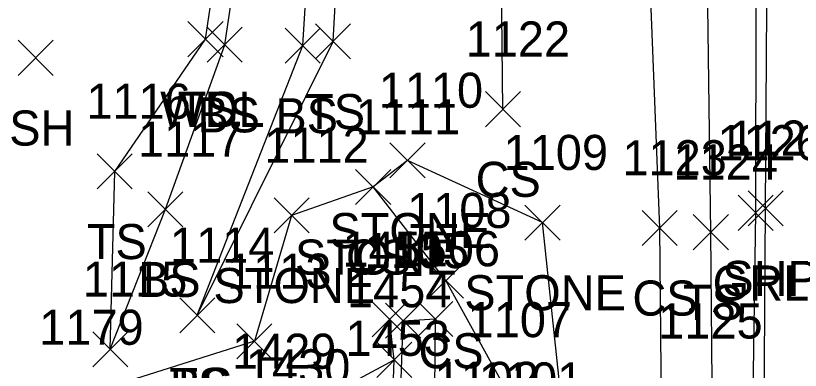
# Model space of a CAD drawing. Extents: x 1618262 to 1622220, y 273782 to 283685.
# Drawn here: x 1622001.44 to 1622046.16, y 282700.39 to 282720.6 of the extents above; entities that cross this region are included whole.
import ezdxf

# ---------------------------------------------------------------- set-up
doc = ezdxf.new("R2010")
doc.units = 0
for name, color, linetype in [('D_I', 7, 'Continuous'), ('D_TIC', 7, 'Continuous'), ('DHW', 7, 'Continuous'), ('L_A', 7, 'Continuous'), ('L_I', 7, 'Continuous'), ('L_TIC', 7, 'Continuous'), ('LASF', 7, 'Continuous'), ('LAWA', 7, 'Continuous'), ('LAWE', 7, 'Continuous'), ('LELB', 7, 'Continuous'), ('P_A', 7, 'Continuous'), ('P_I', 7, 'Continuous'), ('P_TIC', 7, 'Continuous'), ('PSP', 7, 'Continuous'), ('R_A', 7, 'Continuous'), ('R_I', 7, 'Continuous'), ('R_TIC', 7, 'Continuous'), ('RGR', 7, 'Continuous'), ('S_I', 7, 'Continuous')]:
    doc.layers.add(name, color=color, linetype=linetype)

msp = doc.modelspace()

# ---------------------------------------------------------------- linework, layer by layer
at = {"layer": 'D_TIC'}
for points in [[(1622022.527, 282702.211), (1622024.527, 282704.211)], [(1622024.527, 282702.211), (1622022.527, 282704.211)], [(1622024.354, 282702.314), (1622026.354, 282704.314)], [(1622026.354, 282702.314), (1622024.354, 282704.314)]]:
    msp.add_lwpolyline(points, dxfattribs=at)
at = {"layer": 'DHW'}
msp.add_lwpolyline([(1622025.278, 282695.241), (1622023.237, 282694.874), (1622023.527, 282703.211), (1622025.354, 282703.314), (1622025.278, 282695.241)], dxfattribs=at)
at = {"layer": 'L_TIC'}
for points in [[(1622011.261, 282718.262), (1622013.261, 282720.262)], [(1622013.261, 282718.262), (1622011.261, 282720.262)], [(1622011.261, 282718.262), (1622013.261, 282720.262)], [(1622013.261, 282718.262), (1622011.261, 282720.262)], [(1622018.526, 282718.135), (1622020.526, 282720.135)], [(1622020.526, 282718.135), (1622018.526, 282720.135)], [(1622012.354, 282717.948), (1622014.354, 282719.948)], [(1622014.354, 282717.948), (1622012.354, 282719.948)], [(1622016.803, 282717.897), (1622018.803, 282719.897)], [(1622018.803, 282717.897), (1622016.803, 282719.897)], [(1622001.585, 282717.197), (1622003.585, 282719.197)], [(1622003.585, 282717.197), (1622001.585, 282719.197)], [(1622028.212, 282714.273), (1622030.212, 282716.273)], [(1622030.212, 282714.273), (1622028.212, 282716.273)], [(1622022.774, 282711.352), (1622024.774, 282713.352)], [(1622024.774, 282711.352), (1622022.774, 282713.352)], [(1622006.086, 282710.724), (1622008.086, 282712.724)], [(1622008.086, 282710.724), (1622006.086, 282712.724)], [(1622020.815, 282709.839), (1622022.815, 282711.839)], [(1622022.815, 282709.839), (1622020.815, 282711.839)], [(1622020.815, 282709.839), (1622022.815, 282711.839)], [(1622022.815, 282709.839), (1622020.815, 282711.839)], [(1622008.972, 282708.565), (1622010.972, 282710.565)], [(1622010.972, 282708.565), (1622008.972, 282710.565)], [(1622016.17, 282708.218), (1622018.17, 282710.218)], [(1622018.17, 282708.218), (1622016.17, 282710.218)], [(1622030.462, 282707.807), (1622032.462, 282709.807)], [(1622032.462, 282707.807), (1622030.462, 282709.807)], [(1622037.146, 282707.503), (1622039.146, 282709.503)], [(1622039.146, 282707.503), (1622037.146, 282709.503)], [(1622040.057, 282707.261), (1622042.057, 282709.261)], [(1622042.057, 282707.261), (1622040.057, 282709.261)], [(1622024.954, 282704.5), (1622026.954, 282706.5)], [(1622026.954, 282704.5), (1622024.954, 282706.5)], [(1622010.792, 282702.523), (1622012.792, 282704.523)], [(1622012.792, 282702.523), (1622010.792, 282704.523)], [(1622010.792, 282702.523), (1622012.792, 282704.523)], [(1622012.792, 282702.523), (1622010.792, 282704.523)], [(1622021.752, 282702.296), (1622023.752, 282704.296)], [(1622023.752, 282702.296), (1622021.752, 282704.296)], [(1622014.049, 282701.038), (1622016.049, 282703.038)], [(1622016.049, 282701.038), (1622014.049, 282703.038)], [(1622005.83, 282700.587), (1622007.83, 282702.587)], [(1622007.83, 282700.587), (1622005.83, 282702.587)], [(1622005.83, 282700.587), (1622007.83, 282702.587)], [(1622007.83, 282700.587), (1622005.83, 282702.587)], [(1622022.015, 282699.983), (1622024.015, 282701.983)], [(1622024.015, 282699.983), (1622022.015, 282701.983)], [(1622022.015, 282699.983), (1622024.015, 282701.983)], [(1622024.015, 282699.983), (1622022.015, 282701.983)]]:
    msp.add_lwpolyline(points, dxfattribs=at)
at = {"layer": 'LASF'}
msp.add_lwpolyline([(1622017.991, 282482.049), (1622021.545, 282521.435), (1622023.199, 282560.154), (1622027.724, 282598.268), (1622026.162, 282633.945), (1622026.882, 282675.285), (1622029.94, 282679.448), (1622032.966, 282688.79), (1622033.094, 282693.395), (1622031.462, 282708.807), (1622023.774, 282712.352), (1622021.815, 282710.839), (1622017.17, 282709.218), (1622015.049, 282702.038), (1622004.918, 282698.84), (1621996.66, 282681.559), (1622000.409, 282659.069)], dxfattribs=at)
at = {"layer": 'LAWA'}
msp.add_lwpolyline([(1622012.261, 282719.262), (1622015.512, 282741.117), (1622016.402, 282766.923), (1622013.003, 282796.989), (1622009.949, 282826.463), (1622001.868, 282858.825)], dxfattribs=at)
at = {"layer": 'LAWE'}
msp.add_lwpolyline([(1622004.508, 282589.719), (1622005.333, 282608.569), (1622007.513, 282631.716), (1622009.259, 282658.274), (1622005.37, 282679.941), (1622009.389, 282692.601), (1622016.472, 282697.474), (1622023.015, 282700.983)], dxfattribs=at)
at = {"layer": 'LELB'}
for points in [[(1622031.53, 282480.209), (1622034.92, 282519.516), (1622036.308, 282559.668), (1622038.549, 282600.481), (1622040.575, 282634.794), (1622041.384, 282671.626), (1622041.057, 282708.261), (1622040.536, 282746.865), (1622039.334, 282766.475), (1622038.366, 282807.145), (1622036.997, 282847.689), (1622035.465, 282881.364), (1622030.123, 282906.905), (1622032.201, 282930.97)], [(1622011.792, 282703.523), (1622017.803, 282718.897), (1622019.25, 282742.062), (1622019.347, 282767.736), (1622022.846, 282795.877), (1622021.207, 282825.793), (1622021.001, 282858.668), (1622021.577, 282889.835), (1622019.372, 282916.251), (1622019.074, 282930.132)], [(1622006.83, 282701.587), (1622009.972, 282709.565), (1622013.354, 282718.948), (1622016.651, 282741.117), (1622017.648, 282766.711), (1622013.003, 282796.989)], [(1622011.792, 282703.523), (1622019.526, 282719.135), (1622020.798, 282741.845), (1622019.651, 282767.692), (1622022.846, 282795.877)], [(1622038.036, 282634.62), (1622038.492, 282672.044), (1622038.146, 282708.503), (1622036.634, 282747.032), (1622027.782, 282767.08)], [(1622029.212, 282715.273), (1622028.888, 282746.116), (1622027.782, 282767.08)], [(1622006.83, 282701.587), (1622007.086, 282711.724), (1622012.261, 282719.262)], [(1622029.403, 282699.274), (1622025.954, 282705.5), (1622021.815, 282710.839)], [(1622015.253, 282589.258), (1622018.278, 282610.651), (1622017.432, 282626.905), (1622019.353, 282657.587), (1622018.302, 282675.18), (1622022.753, 282682.471), (1622023.259, 282685.553), (1622022.974, 282687.958), (1622023.158, 282690.363), (1622022.911, 282694.814), (1622022.926, 282698.21), (1622023.015, 282700.983), (1622022.752, 282703.296)]]:
    msp.add_lwpolyline(points, dxfattribs=at)
at = {"layer": 'P_TIC'}
for points in [[(1622043.179, 282708.624), (1622045.179, 282710.624)], [(1622045.179, 282708.624), (1622043.179, 282710.624)]]:
    msp.add_lwpolyline(points, dxfattribs=at)
at = {"layer": 'PSP'}
msp.add_lwpolyline([(1622024.53, 282364.695), (1622029.224, 282410.341), (1622032.133, 282444.404), (1622034.721, 282480.169), (1622038.065, 282518.937), (1622040.189, 282559.981), (1622041.775, 282599.797), (1622043.576, 282635.077), (1622043.931, 282671.705), (1622044.179, 282709.624), (1622044.427, 282746.882), (1622044.138, 282766.852), (1622043.312, 282807.356), (1622042.106, 282847.846), (1622040.006, 282882.115), (1622036.278, 282931.352)], dxfattribs=at)
at = {"layer": 'R_TIC'}
for points in [[(1622042.615, 282708.363), (1622044.615, 282710.363)], [(1622044.615, 282708.363), (1622042.615, 282710.363)]]:
    msp.add_lwpolyline(points, dxfattribs=at)
at = {"layer": 'RGR'}
msp.add_lwpolyline([(1622023.476, 282364.894), (1622028.185, 282410.184), (1622031.232, 282444.188), (1622033.737, 282480.242), (1622036.802, 282518.899), (1622039.036, 282560.065), (1622040.978, 282599.772), (1622042.921, 282635.171), (1622043.063, 282671.763), (1622043.615, 282709.363), (1622043.681, 282746.97), (1622043.35, 282766.727), (1622042.763, 282807.193), (1622041.251, 282847.718), (1622039.436, 282882.181), (1622035.129, 282907.981)], dxfattribs=at)

# ---------------------------------------------------------------- texts
at = {"layer": 'D_I'}
for s, p in [('1105', (1622021.323, 282706.211)), ('1106', (1622023.094, 282706.314))]:
    msp.add_text(s, height=2, dxfattribs=at).set_placement(p)
at = {"layer": 'L_A'}
for s, p in [('WDL', (1622009.679, 282714.262)), ('TS', (1622010.671, 282714.262)), ('TS', (1622017.935, 282714.135)), ('BS', (1622011.795, 282713.948)), ('BS', (1622016.244, 282713.897)), ('SH', (1622001.074, 282713.197)), ('CS', (1622027.653, 282710.273)), ('STONE', (1622019.318, 282707.352)), ('TS', (1622005.495, 282706.724)), ('STONE', (1622017.358, 282705.839)), ('CS', (1622020.256, 282705.839)), ('BS', (1622008.413, 282704.565)), ('STONE', (1622012.713, 282704.218)), ('STONE', (1622027.005, 282703.807)), ('CS', (1622036.587, 282703.503)), ('TS', (1622039.467, 282703.261)), ('CS', (1622024.395, 282700.5)), ('TS', (1622010.202, 282698.523)), ('BS', (1622010.233, 282698.523))]:
    msp.add_text(s, height=2, dxfattribs=at).set_placement(p)
at = {"layer": 'L_I'}
for s, p in [('1122', (1622027.087, 282718.273)), ('1110', (1622022.129, 282715.352)), ('1116', (1622005.472, 282714.724)), ('1111', (1622020.823, 282713.839)), ('1111', (1622020.823, 282713.839)), ('1117', (1622008.413, 282712.565)), ('1112', (1622015.611, 282712.218)), ('1109', (1622029.249, 282711.807)), ('1123', (1622036.021, 282711.503)), ('1124', (1622038.931, 282711.261)), ('1108', (1622023.749, 282708.5)), ('1114', (1622010.233, 282706.523)), ('1114', (1622010.233, 282706.523)), ('1455', (1622020.06, 282706.296)), ('1113', (1622013.491, 282705.038)), ('1115', (1622005.271, 282704.587)), ('1115', (1622005.271, 282704.587)), ('1454', (1622020.322, 282703.983)), ('1454', (1622020.322, 282703.983)), ('1107', (1622027.199, 282702.274)), ('1179', (1622002.785, 282701.84)), ('1453', (1622020.234, 282701.21)), ('1453', (1622020.234, 282701.21)), ('1429', (1622013.771, 282700.474)), ('1430', (1622014.563, 282699.584)), ('1102', (1622025.314, 282698.871)), ('1101', (1622027.841, 282698.837))]:
    msp.add_text(s, height=2, dxfattribs=at).set_placement(p)
at = {"layer": 'P_A'}
msp.add_text('SHP', height=2, dxfattribs=at).set_placement((1622041.715, 282704.624))
at = {"layer": 'P_I'}
msp.add_text('1127', height=2, dxfattribs=at).set_placement((1622042.054, 282712.624))
at = {"layer": 'R_A'}
msp.add_text('GRL', height=2, dxfattribs=at).set_placement((1622041.159, 282704.363))
at = {"layer": 'R_I'}
msp.add_text('1126', height=2, dxfattribs=at).set_placement((1622041.434, 282712.363))
at = {"layer": 'S_I'}
msp.add_text('1125', height=2, dxfattribs=at).set_placement((1622038.06, 282702.198))

doc.saveas('drawing.dxf')
